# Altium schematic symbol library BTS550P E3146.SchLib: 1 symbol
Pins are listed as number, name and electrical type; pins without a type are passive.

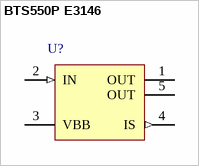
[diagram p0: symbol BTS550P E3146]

## BTS550P E3146
designator U?
Smart High-Side High Current Power Switch, 1 Channel, 35 A Load Current, -40 to 150 degC, P-TO218-5-146, Reel, Green; Manufacturer: Infineon; PartNumber: BTS550P E3146; Channels: 1; Green: TRUE; Group: Automotive Qualified; Load Current (typ): 35 A; Ptot (max): 360 W; Recommended Operating Voltage Max.: 34 V; Recommended Operating Voltage Min.: 5 V; RON @ 25degreesC: 3.6 mOhm; RON(max) @ 150degreesC: 6.5 mOhm; toff (max): 150 us; ton (max): 600 us
footprint INF-P-TO218-5-146 (FM, 5-Leads, Body 15x12.5mm, Pitch 2.54mm)
pins: 1 OUT (power) "Output to the load. The pins1 and 5 must be shorted with each other especially in high current applications!", 2 IN (in) "Input, activates the power switch in case of short to ground", 3 VBB (power) "Positive power supply voltage, the tab is electrically connected to this pin.In high current applications the tab should be used for the Vbb connection instead of this pin", 4 IS (out) "Diagnostic feedback providing a sense current proportional to the load current; zero current on failure (see Truth Table on page 7)", 5 OUT (power) "Output to the load. The pins1 and 5 must be shorted with each other especially in high current applications!"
